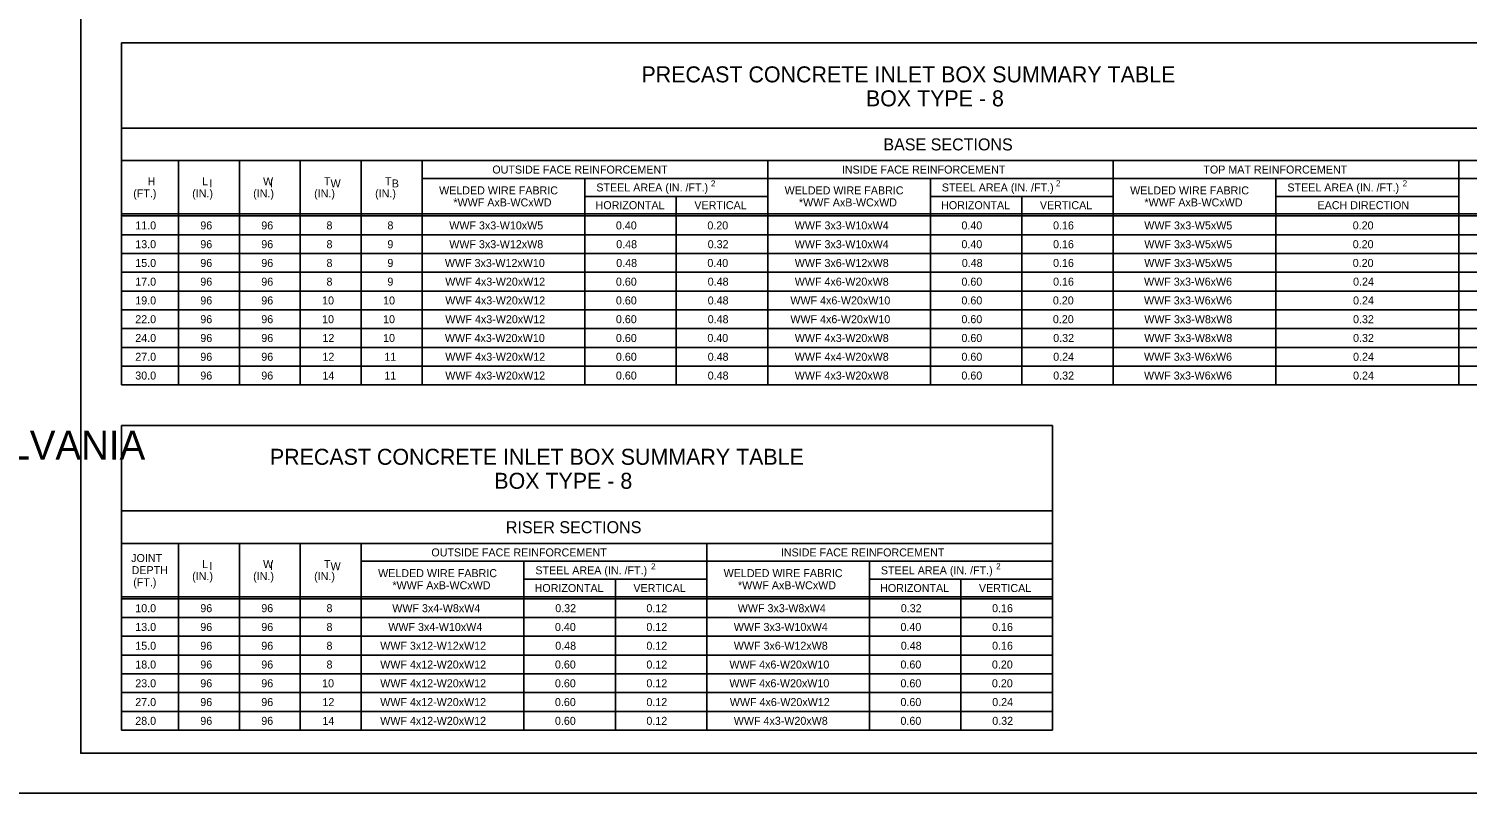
# Model space of a CAD drawing. Extents: x -6420 to 49575, y -4552 to 11624.
# Drawn here: x -838 to 931, y -2018 to -1077 of the extents above; entities that cross this region are included whole.
import ezdxf

# ---------------------------------------------------------------- set-up
doc = ezdxf.new("R2010")
doc.units = 0
doc.layers.add('1', color=7, linetype='Continuous')
doc.layers.add('PLT-BNDY', color=7, linetype='Continuous')

msp = doc.modelspace()

# ---------------------------------------------------------------- linework, layer by layer
at = {"layer": '1'}
for p, q in [((-724, -1094.6), (-724, -1515.6)), ((1346, -1094.6), (-724, -1094.6)), ((1346, -1199.6), (-724, -1199.6)), ((1346, -1239.6), (-724, -1239.6)), ((-654, -1515.6), (-654, -1239.6)), ((-579, -1239.6), (-579, -1515.6)), ((-504, -1239.6), (-504, -1515.6)), ((-429, -1239.6), (-429, -1515.6)), ((-354, -1239.6), (-354, -1515.6)), ((71, -1239.6), (71, -1515.6)), ((496, -1239.6), (496, -1515.6)), ((921, -1239.6), (921, -1515.6)), ((-354, -1261.6), (71, -1261.6)), ((-154, -1261.6), (-154, -1515.6)), ((71, -1261.6), (1346, -1261.6)), ((271, -1261.6), (271, -1515.6)), ((696, -1261.6), (696, -1515.6)), ((-154, -1283.6), (71, -1283.6)), ((-41.5, -1283.6), (-41.5, -1515.6)), ((271, -1283.6), (496, -1283.6)), ((383.5, -1283.6), (383.5, -1515.6)), ((696, -1283.6), (921, -1283.6)), ((-724, -1305.2), (1346, -1305.2)), ((-724, -1307.7), (1346, -1307.7)), ((-724, -1330.8), (1346, -1330.8)), ((-724, -1353.9), (1346, -1353.9)), ((-724, -1377), (1346, -1377)), ((-724, -1400.1), (1346, -1400.1)), ((-724, -1423.2), (1346, -1423.2)), ((-724, -1446.3), (1346, -1446.3)), ((-724, -1469.4), (1346, -1469.4)), ((-724, -1492.5), (1346, -1492.5)), ((-724, -1515.6), (1346, -1515.6)), ((-724, -1565.6), (-724, -1940.3)), ((421, -1565.6), (-724, -1565.6)), ((421, -1565.6), (421, -1940.3)), ((421, -1670.5), (-724, -1670.5)), ((421, -1710.5), (-724, -1710.5)), ((-654, -1940.3), (-654, -1710.5)), ((-579, -1710.5), (-579, -1940.3)), ((-504, -1710.5), (-504, -1940.3)), ((-429, -1710.5), (-429, -1940.3)), ((-4, -1710.5), (-4, -1940.3)), ((-429, -1732.5), (-4, -1732.5)), ((-229, -1732.5), (-229, -1940.3)), ((-4, -1732.5), (421, -1732.5)), ((196, -1732.5), (196, -1940.3)), ((-229, -1754.5), (-4, -1754.5)), ((-116.5, -1754.5), (-116.5, -1940.3)), ((196, -1754.5), (421, -1754.5)), ((308.5, -1754.5), (308.5, -1940.3)), ((-724, -1776.2), (421, -1776.2)), ((-724, -1778.6), (421, -1778.6)), ((-724, -1801.7), (421, -1801.7)), ((-724, -1824.8), (421, -1824.8)), ((-724, -1847.9), (421, -1847.9)), ((-724, -1871), (421, -1871)), ((-724, -1894.1), (421, -1894.1)), ((-724, -1917.2), (421, -1917.2)), ((-724, -1940.3), (421, -1940.3))]:
    msp.add_line(p, q, dxfattribs=at)
msp.add_lwpolyline([(1804.7, -1968.6), (1804.7, -118.2), (-774, -118.2), (-774, -1968.6), (1804.7, -1968.6), (1804.7, -1882.1), (1148.5, -1882.1), (1148.5, -1669.9), (1804.7, -1669.9), (1804.7, -1574.9), (1148.5, -1574.9), (1148.5, -1968.6), (1407.1, -1968.6), (1407.1, -1882.1), (1407.1, -1968.6), (1659.7, -1968.6), (1659.7, -1882.1), (1659.7, -1922.6), (1804.7, -1922.6)], dxfattribs=at)
at = {"layer": 'PLT-BNDY'}
msp.add_lwpolyline([(-902, -69), (1857.2, -69), (1857.2, -2017.8), (-902, -2017.8)], close=True, dxfattribs=at)

# ---------------------------------------------------------------- texts
at = {"layer": '1'}
for s, height, p in [('PRECAST CONCRETE INLET BOX SUMMARY TABLE', 19.685, (-84.4, -1143.3)), ('BOX TYPE - 8', 19.685, (191.7, -1172.8)), ('BASE SECTIONS', 14.764, (213.2, -1227)), ('OUTSIDE FACE REINFORCEMENT', 9.843, (-267.8, -1255.5)), ('INSIDE FACE REINFORCEMENT', 9.843, (162.1, -1255.5)), ('TOP MAT REINFORCEMENT', 9.843, (606.8, -1255.5)), ('H', 9.84, (-691.8, -1269.9)), ('L ', 9.84, (-624.8, -1269.9)), ('I', 9.84, (-615.7, -1272.5)), ('W ', 9.84, (-549.8, -1269.9)), ('I', 9.84, (-541.4, -1272.4)), ('T ', 9.84, (-474.8, -1269.9)), ('W', 9.84, (-466.8, -1272.6)), ('T ', 9.84, (-399.8, -1269.9)), ('B', 9.84, (-391.5, -1272.6)), ('WELDED WIRE FABRIC', 9.843, (-333.3, -1281.1)), ('STEEL AREA (IN. /FT.)', 9.843, (-139.9, -1277.5)), ('2', 7.5, (1, -1271.4)), ('WELDED WIRE FABRIC', 9.843, (91.7, -1281.1)), ('STEEL AREA (IN. /FT.)', 9.843, (285.1, -1277.5)), ('2', 7.5, (425.5, -1271.2)), ('WELDED WIRE FABRIC', 9.843, (516.7, -1281.1)), ('STEEL AREA (IN. /FT.)', 9.843, (710.1, -1277.5)), ('2', 7.5, (851.9, -1271.2)), ('(FT.)', 9.84, (-709.5, -1284.8)), ('(IN.)', 9.84, (-637, -1284.8)), ('(IN.)', 9.84, (-562, -1284.8)), ('(IN.)', 9.84, (-487, -1284.8)), ('(IN.)', 9.84, (-412, -1284.8)), ('*WWF AxB-WCxWD', 9.843, (-315.7, -1295.9)), ('HORIZONTAL', 9.84, (-140.8, -1299.3)), ('VERTICAL', 9.84, (-19.3, -1299.3)), ('*WWF AxB-WCxWD', 9.843, (109.3, -1295.9)), ('HORIZONTAL', 9.84, (284.2, -1299.3)), ('VERTICAL', 9.84, (405.7, -1299.3)), ('*WWF AxB-WCxWD', 9.843, (534.3, -1295.9)), ('EACH DIRECTION', 9.843, (747.2, -1299.3)), ('11.0', 9.84, (-707, -1324.2)), ('96', 9.84, (-627, -1324.2)), ('96', 9.84, (-552, -1324.2)), ('8', 9.84, (-471.8, -1324.2)), ('8', 9.84, (-396.8, -1324.2)), ('WWF 3x3-W10xW5', 9.843, (-320.8, -1324.2)), ('0.40', 9.84, (-115.8, -1324.2)), ('0.20', 9.84, (-3.3, -1324.2)), ('WWF 3x3-W10xW4', 9.843, (104.2, -1324.2)), ('0.40', 9.84, (309.2, -1324.2)), ('0.16', 9.84, (421.9, -1324.2)), ('WWF 3x3-W5xW5', 9.843, (534.1, -1324.2)), ('0.20', 9.84, (790.5, -1324.2)), ('13.0', 9.84, (-707, -1347.3)), ('96', 9.84, (-627, -1347.3)), ('96', 9.84, (-552, -1347.3)), ('8', 9.84, (-471.8, -1347.3)), ('9', 9.84, (-396.9, -1347.3)), ('WWF 3x3-W12xW8', 9.843, (-320.8, -1347.3)), ('0.48', 9.84, (-115.4, -1347.3)), ('0.32', 9.84, (-2.9, -1347.3)), ('WWF 3x3-W10xW4', 9.843, (104.2, -1347.3)), ('0.40', 9.84, (309.2, -1347.3)), ('0.16', 9.84, (421.9, -1347.3)), ('WWF 3x3-W5xW5', 9.843, (534.1, -1347.3)), ('0.20', 9.84, (790.5, -1347.3)), ('15.0', 9.84, (-707, -1370.4)), ('96', 9.84, (-627, -1370.4)), ('96', 9.84, (-552, -1370.4)), ('8', 9.84, (-471.8, -1370.4)), ('9', 9.84, (-396.9, -1370.4)), ('WWF 3x3-W12xW10', 9.843, (-326.2, -1370.4)), ('0.48', 9.84, (-115.4, -1370.4)), ('0.40', 9.84, (-3.3, -1370.4)), ('WWF 3x6-W12xW8', 9.843, (104.2, -1370.4)), ('0.48', 9.84, (309.6, -1370.4)), ('0.16', 9.84, (421.9, -1370.4)), ('WWF 3x3-W5xW5', 9.843, (534.1, -1370.4)), ('0.20', 9.84, (790.5, -1370.4)), ('17.0', 9.84, (-707, -1393.4)), ('96', 9.84, (-627, -1393.4)), ('96', 9.84, (-552, -1393.4)), ('8', 9.84, (-471.8, -1393.4)), ('9', 9.84, (-396.9, -1393.4)), ('WWF 4x3-W20xW12', 9.843, (-325.7, -1393.4)), ('0.60', 9.84, (-115.8, -1393.4)), ('0.48', 9.84, (-2.9, -1393.4)), ('WWF 4x6-W20xW8', 9.843, (104.2, -1393.4)), ('0.60', 9.84, (309.2, -1393.4)), ('0.16', 9.84, (421.9, -1393.4)), ('WWF 3x3-W6xW6', 9.843, (533.8, -1393.4)), ('0.24', 9.84, (790.9, -1393.4)), ('19.0', 9.84, (-707, -1416.5)), ('96', 9.84, (-627, -1416.5)), ('96', 9.84, (-552, -1416.5)), ('10', 9.84, (-477.2, -1416.5)), ('10', 9.84, (-402.2, -1416.5)), ('WWF 4x3-W20xW12', 9.843, (-325.7, -1416.5)), ('0.60', 9.84, (-115.8, -1416.5)), ('0.48', 9.84, (-2.9, -1416.5)), ('WWF 4x6-W20xW10', 9.843, (98.8, -1416.5)), ('0.60', 9.84, (309.2, -1416.5)), ('0.20', 9.84, (421.7, -1416.5)), ('WWF 3x3-W6xW6', 9.843, (533.8, -1416.5)), ('0.24', 9.84, (790.9, -1416.5)), ('22.0', 9.84, (-707, -1439.6)), ('96', 9.84, (-627, -1439.6)), ('96', 9.84, (-552, -1439.6)), ('10', 9.84, (-477.2, -1439.6)), ('10', 9.84, (-402.2, -1439.6)), ('WWF 4x3-W20xW12', 9.843, (-325.7, -1439.6)), ('0.60', 9.84, (-115.8, -1439.6)), ('0.48', 9.84, (-2.9, -1439.6)), ('WWF 4x6-W20xW10', 9.843, (98.8, -1439.6)), ('0.60', 9.84, (309.2, -1439.6)), ('0.20', 9.84, (421.7, -1439.6)), ('WWF 3x3-W8xW8', 9.843, (534.1, -1439.6)), ('0.32', 9.84, (790.9, -1439.6)), ('24.0', 9.84, (-707, -1462.7)), ('96', 9.84, (-627, -1462.7)), ('96', 9.84, (-552, -1462.7)), ('12', 9.84, (-476.8, -1462.7)), ('10', 9.84, (-402.2, -1462.7)), ('WWF 4x3-W20xW10', 9.843, (-326.2, -1462.7)), ('0.60', 9.84, (-115.8, -1462.7)), ('0.40', 9.84, (-3.3, -1462.7)), ('WWF 4x3-W20xW8', 9.843, (104.2, -1462.7)), ('0.60', 9.84, (309.2, -1462.7)), ('0.32', 9.84, (422.1, -1462.7)), ('WWF 3x3-W8xW8', 9.843, (534.1, -1462.7)), ('0.32', 9.84, (790.9, -1462.7)), ('27.0', 9.84, (-707, -1485.8)), ('96', 9.84, (-627, -1485.8)), ('96', 9.84, (-552, -1485.8)), ('12', 9.84, (-476.8, -1485.8)), ('11', 9.84, (-400.6, -1485.8)), ('WWF 4x3-W20xW12', 9.843, (-325.7, -1485.8)), ('0.60', 9.84, (-115.8, -1485.8)), ('0.48', 9.84, (-2.9, -1485.8)), ('WWF 4x4-W20xW8', 9.843, (104.2, -1485.8)), ('0.60', 9.84, (309.2, -1485.8)), ('0.24', 9.84, (422.1, -1485.8)), ('WWF 3x3-W6xW6', 9.843, (533.8, -1485.8)), ('0.24', 9.84, (790.9, -1485.8)), ('30.0', 9.84, (-707, -1508.9)), ('96', 9.84, (-627, -1508.9)), ('96', 9.84, (-552, -1508.9)), ('14', 9.84, (-476.8, -1508.9)), ('11', 9.84, (-400.6, -1508.9)), ('WWF 4x3-W20xW12', 9.843, (-325.7, -1508.9)), ('0.60', 9.84, (-115.8, -1508.9)), ('0.48', 9.84, (-2.9, -1508.9)), ('WWF 4x3-W20xW8', 9.843, (104.2, -1508.9)), ('0.60', 9.84, (309.2, -1508.9)), ('0.32', 9.84, (422.1, -1508.9)), ('WWF 3x3-W6xW6', 9.843, (533.8, -1508.9)), ('0.24', 9.84, (790.9, -1508.9)), ('COMMONWEALTH OF PENNSYLVANIA', 35.379, (-1567.5, -1607.3)), ('PRECAST CONCRETE INLET BOX SUMMARY TABLE', 19.685, (-541.4, -1613.8)), ('BOX TYPE - 8', 19.685, (-265.4, -1643.3)), ('RISER SECTIONS', 14.764, (-251.2, -1697.9)), ('JOINT', 9.84, (-712, -1733.4)), ('L ', 9.84, (-624.8, -1740.9)), ('I', 9.84, (-615.7, -1743.4)), ('W ', 9.84, (-549.8, -1740.9)), ('I', 9.84, (-541.4, -1743.4)), ('T ', 9.84, (-474.8, -1740.9)), ('W', 9.84, (-466.8, -1743.5)), ('OUTSIDE FACE REINFORCEMENT', 9.843, (-342.8, -1726.5)), ('INSIDE FACE REINFORCEMENT', 9.843, (87.1, -1726.5)), ('DEPTH', 9.84, (-711.5, -1748.3)), ('(IN.)', 9.84, (-637, -1755.7)), ('(IN.)', 9.84, (-562, -1755.7)), ('(IN.)', 9.84, (-487, -1755.7)), ('WELDED WIRE FABRIC', 9.843, (-408.3, -1752)), ('STEEL AREA (IN. /FT.)', 9.843, (-214.9, -1748.5)), ('2', 7.5, (-72.6, -1742.4)), ('WELDED WIRE FABRIC', 9.843, (16.7, -1752)), ('STEEL AREA (IN. /FT.)', 9.843, (210.1, -1748.5)), ('2', 7.5, (351.9, -1742.4)), ('(FT.)', 9.84, (-709.5, -1763.1)), ('*WWF AxB-WCxWD', 9.843, (-390.7, -1766.9)), ('HORIZONTAL', 9.84, (-215.8, -1770.3)), ('VERTICAL', 9.84, (-94.3, -1770.3)), ('*WWF AxB-WCxWD', 9.843, (34.3, -1766.9)), ('HORIZONTAL', 9.84, (209.2, -1770.3)), ('VERTICAL', 9.84, (330.7, -1770.3)), ('10.0', 9.84, (-707, -1795.1)), ('96', 9.84, (-627, -1795.1)), ('96', 9.84, (-552, -1795.1)), ('8', 9.84, (-471.8, -1795.1)), ('WWF 3x4-W8xW4', 9.843, (-390.9, -1795.1)), ('0.32', 9.84, (-190.4, -1795.1)), ('0.12', 9.84, (-78.3, -1795.1)), ('WWF 3x3-W8xW4', 9.843, (34.1, -1795.1)), ('0.32', 9.84, (234.6, -1795.1)), ('0.16', 9.84, (346.9, -1795.1)), ('13.0', 9.84, (-707, -1818.2)), ('96', 9.84, (-627, -1818.2)), ('96', 9.84, (-552, -1818.2)), ('8', 9.84, (-471.8, -1818.2)), ('WWF 3x4-W10xW4', 9.843, (-395.8, -1818.2)), ('0.40', 9.84, (-190.8, -1818.2)), ('0.12', 9.84, (-78.3, -1818.2)), ('WWF 3x3-W10xW4', 9.843, (29.2, -1818.2)), ('0.40', 9.84, (234.2, -1818.2)), ('0.16', 9.84, (346.9, -1818.2)), ('15.0', 9.84, (-707, -1841.3)), ('96', 9.84, (-627, -1841.3)), ('96', 9.84, (-552, -1841.3)), ('8', 9.84, (-471.8, -1841.3)), ('WWF 3x12-W12xW12', 9.843, (-405.7, -1841.3)), ('0.48', 9.84, (-190.4, -1841.3)), ('0.12', 9.84, (-78.3, -1841.3)), ('WWF 3x6-W12xW8', 9.843, (29.2, -1841.3)), ('0.48', 9.84, (234.6, -1841.3)), ('0.16', 9.84, (346.9, -1841.3)), ('18.0', 9.84, (-707, -1864.4)), ('96', 9.84, (-627, -1864.4)), ('96', 9.84, (-552, -1864.4)), ('8', 9.84, (-471.8, -1864.4)), ('WWF 4x12-W20xW12', 9.843, (-405.7, -1864.4)), ('0.60', 9.84, (-190.8, -1864.4)), ('0.12', 9.84, (-78.3, -1864.4)), ('WWF 4x6-W20xW10', 9.843, (23.8, -1864.4)), ('0.60', 9.84, (234.2, -1864.4)), ('0.20', 9.84, (346.7, -1864.4)), ('23.0', 9.84, (-707, -1887.5)), ('96', 9.84, (-627, -1887.5)), ('96', 9.84, (-552, -1887.5)), ('10', 9.84, (-477.2, -1887.5)), ('WWF 4x12-W20xW12', 9.843, (-405.7, -1887.5)), ('0.60', 9.84, (-190.8, -1887.5)), ('0.12', 9.84, (-78.3, -1887.5)), ('WWF 4x6-W20xW10', 9.843, (23.8, -1887.5)), ('0.60', 9.84, (234.2, -1887.5)), ('0.20', 9.84, (346.7, -1887.5)), ('27.0', 9.84, (-707, -1910.6)), ('96', 9.84, (-627, -1910.6)), ('96', 9.84, (-552, -1910.6)), ('12', 9.84, (-476.8, -1910.6)), ('WWF 4x12-W20xW12', 9.843, (-405.7, -1910.6)), ('0.60', 9.84, (-190.8, -1910.6)), ('0.12', 9.84, (-78.3, -1910.6)), ('WWF 4x6-W20xW12', 9.843, (24.3, -1910.6)), ('0.60', 9.84, (234.2, -1910.6)), ('0.24', 9.84, (347.1, -1910.6)), ('28.0', 9.84, (-707, -1933.7)), ('96', 9.84, (-627, -1933.7)), ('96', 9.84, (-552, -1933.7)), ('14', 9.84, (-476.8, -1933.7)), ('WWF 4x12-W20xW12', 9.843, (-405.7, -1933.7)), ('0.60', 9.84, (-190.8, -1933.7)), ('0.12', 9.84, (-78.3, -1933.7)), ('WWF 4x3-W20xW8', 9.843, (29.2, -1933.7)), ('0.60', 9.84, (234.2, -1933.7)), ('0.32', 9.84, (347.1, -1933.7))]:
    msp.add_text(s, height=height, dxfattribs=at).set_placement(p)

doc.saveas('drawing.dxf')
